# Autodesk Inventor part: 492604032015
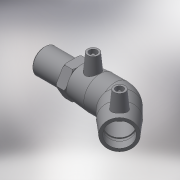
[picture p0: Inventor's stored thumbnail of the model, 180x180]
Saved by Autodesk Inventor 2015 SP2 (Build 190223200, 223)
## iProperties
Created: 2017-06
Part Number: 492604032015
Material: Generic
Description: PLASSON 45° ELBOW TRANSITION MALE 32-1.1/2"
Document SubType Name: Modeling
Designer: KIM
Mass: 130.874 g
Surface Area: 382.97 cm^2
Volume: 130.874 cm^3
Density: 1 g/cm^3
Appearance: Default
Author: KIM
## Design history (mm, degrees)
derived "492604.ipt"
feature "Solid1::492604.ipt"
tag "TaggingFeature1"
body "Solid1"
other parameters: "d2" = 44, "d4" = 23.5, "d5" = 39.6, "d8" = 168 deg, "d10" = 15.6, "d11" = 5.2, "d29" = 43, "d30" = 15, "d31" = 32.9, "d34" = 5 deg, "d41" = 4, "d42" = 14, "d43" = 0, "d49" = 32, "d50" = 20.8, "d51" = 15.6, "d52" = 40.17, "d54" = 135 deg, "d86" = 19.8, "d87" = 135 deg, "d88" = 94, "d90" = 39, "d91" = 0, "d92" = 39, "d93" = 0, "d101" = 3, "d102" = 0, "d107" = 0.1, "d108" = 23, "d109" = 47.803, "d110" = 36, "d111" = 9, "d112" = 57.2, "d113" = 33.4621, "d114" = 32.4, "d116" = 1.32, "d122" = 0, "d123" = 2.39015, "d_" = 32, "L_1" = 39, "D_" = 23, "A_" = 43, "d_2" = 12, "L_2" = 36, "R_" = 47.803, "D_1" = 44
